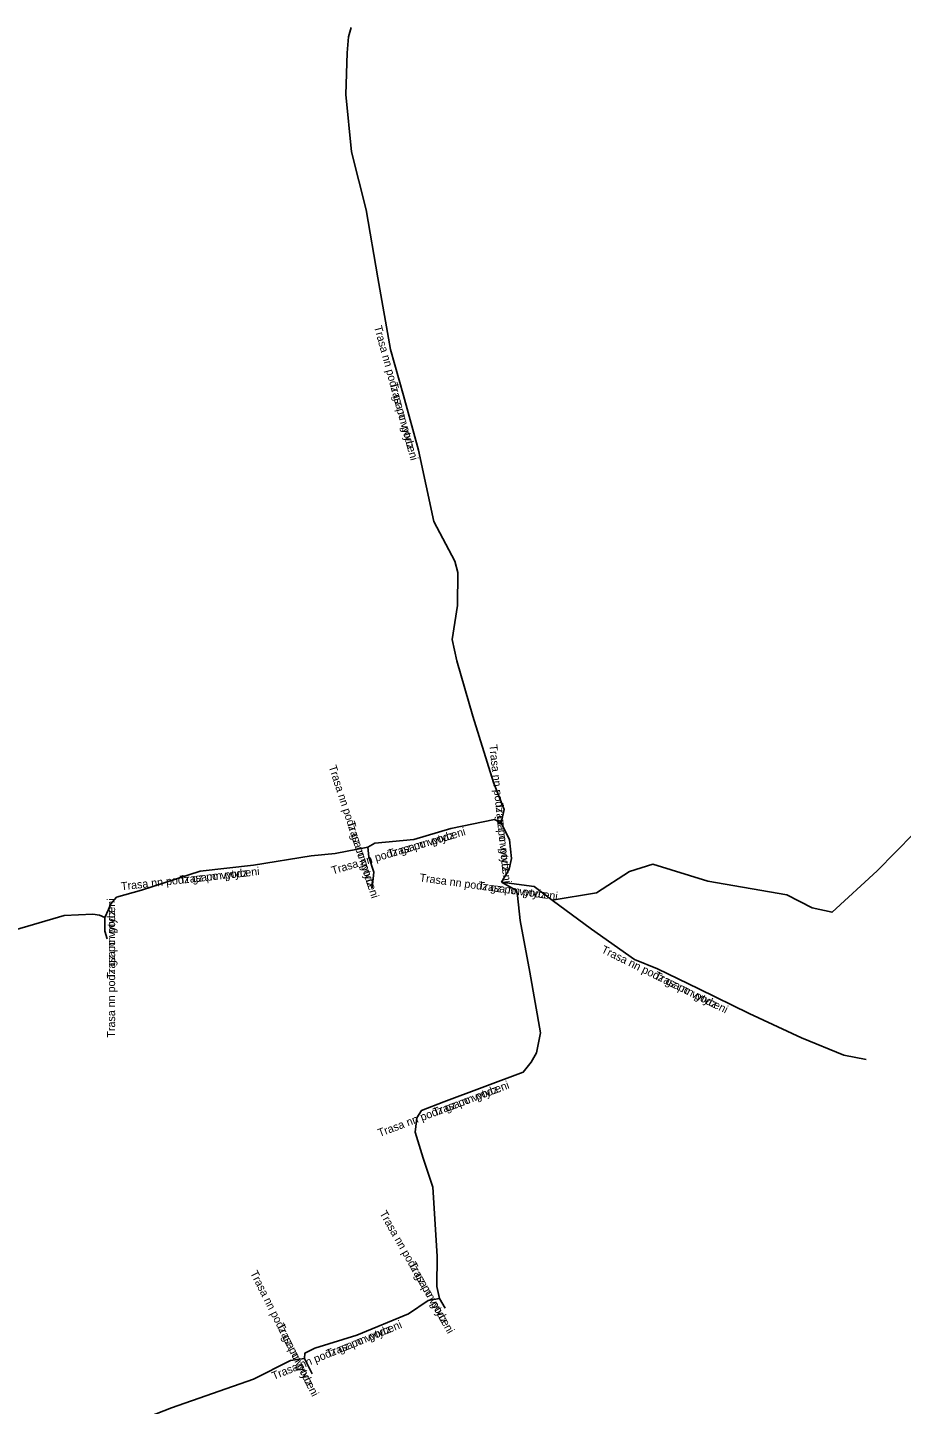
# Model space of a CAD drawing. Extents: x -876384 to -875659, y -1020218 to -1019588.
# Drawn here: x -875808.4 to -875753.8, y -1019934.5 to -1019848.4 of the extents above; entities that cross this region are included whole.
import ezdxf

# ---------------------------------------------------------------- set-up
doc = ezdxf.new("R2010")
doc.units = 0
doc.layers.add('Popiskový text - Ostatní atributy Trasy', color=7, linetype='Continuous')
doc.layers.add('Spojnice NN', color=7, linetype='Continuous')

msp = doc.modelspace()

# ---------------------------------------------------------------- linework, layer by layer
at = {"layer": 'Spojnice NN'}
for points in [[(-875788.21, -1019848.44), (-875788.36, -1019849.03), (-875788.44, -1019850.01), (-875788.54, -1019852.62), (-875788.18, -1019856.21), (-875787.27, -1019859.83), (-875786.53, -1019864.07), (-875785.75, -1019868.56), (-875784.93, -1019871.42), (-875783.99, -1019874.85), (-875783.03, -1019879.31), (-875781.73, -1019881.79), (-875781.53, -1019882.48), (-875781.57, -1019884.56), (-875781.9, -1019886.67), (-875781.6, -1019888.01), (-875780.6, -1019891.46), (-875779.31, -1019895.61), (-875778.65, -1019897.3), (-875778.83, -1019898.12)], [(-875788.21, -1019848.44), (-875788.36, -1019849.03), (-875788.44, -1019850.01), (-875788.54, -1019852.62), (-875788.18, -1019856.21), (-875787.27, -1019859.83), (-875786.53, -1019864.07), (-875785.75, -1019868.56), (-875784.93, -1019871.42), (-875783.99, -1019874.85), (-875783.03, -1019879.31), (-875781.73, -1019881.79), (-875781.53, -1019882.48), (-875781.57, -1019884.56), (-875781.9, -1019886.67), (-875781.6, -1019888.01), (-875780.6, -1019891.46), (-875779.31, -1019895.61), (-875778.65, -1019897.3), (-875778.83, -1019898.12)], [(-875787.16, -1019899.65), (-875786.73, -1019899.4), (-875784.29, -1019899.18), (-875781.97, -1019898.49), (-875779.24, -1019897.92), (-875778.83, -1019898.12)], [(-875787.16, -1019899.65), (-875786.73, -1019899.4), (-875784.29, -1019899.18), (-875781.97, -1019898.49), (-875779.24, -1019897.92), (-875778.83, -1019898.12)], [(-875778.83, -1019898.12), (-875778.31, -1019899.19), (-875778.19, -1019900.35), (-875778.33, -1019901.03), (-875778.82, -1019901.83)], [(-875778.83, -1019898.12), (-875778.31, -1019899.19), (-875778.19, -1019900.35), (-875778.33, -1019901.03), (-875778.82, -1019901.83)], [(-875775.64, -1019902.96), (-875772.88, -1019902.51), (-875770.81, -1019901.17), (-875769.37, -1019900.71), (-875765.93, -1019901.77), (-875760.99, -1019902.62), (-875759.42, -1019903.43), (-875758.17, -1019903.72), (-875755.35, -1019901.12), (-875753.07, -1019898.79)], [(-875775.64, -1019902.96), (-875772.88, -1019902.51), (-875770.81, -1019901.17), (-875769.37, -1019900.71), (-875765.93, -1019901.77), (-875760.99, -1019902.62), (-875759.42, -1019903.43), (-875758.17, -1019903.72), (-875755.35, -1019901.12), (-875753.07, -1019898.79)], [(-875803.59, -1019904.04), (-875803.35, -1019903.55), (-875803.2, -1019903.18), (-875802.85, -1019902.77), (-875801.3, -1019902.34), (-875797.64, -1019901.15), (-875794.3, -1019900.78), (-875790.7, -1019900.19), (-875789.2, -1019900.05), (-875787.16, -1019899.65)], [(-875803.59, -1019904.04), (-875803.35, -1019903.55), (-875803.2, -1019903.18), (-875802.85, -1019902.77), (-875801.3, -1019902.34), (-875797.64, -1019901.15), (-875794.3, -1019900.78), (-875790.7, -1019900.19), (-875789.2, -1019900.05), (-875787.16, -1019899.65)], [(-875786.89, -1019902.2), (-875786.78, -1019901.21), (-875787.09, -1019900.26), (-875787.16, -1019899.65)], [(-875786.89, -1019902.2), (-875786.78, -1019901.21), (-875787.09, -1019900.26), (-875787.16, -1019899.65)], [(-875782.68, -1019927.85), (-875782.86, -1019927.09), (-875782.83, -1019925.2), (-875783.11, -1019920.89), (-875783.7, -1019919.08), (-875784.2, -1019917.46), (-875784.1, -1019916.57), (-875783.8, -1019916.1), (-875782.41, -1019915.56), (-875777.45, -1019913.7), (-875776.95, -1019913.08), (-875776.62, -1019912.5), (-875776.38, -1019911.26), (-875777.04, -1019907.46), (-875777.65, -1019904.23), (-875777.82, -1019902.66), (-875777.88, -1019902.35), (-875778.82, -1019901.83)], [(-875782.68, -1019927.85), (-875782.86, -1019927.09), (-875782.83, -1019925.2), (-875783.11, -1019920.89), (-875783.7, -1019919.08), (-875784.2, -1019917.46), (-875784.1, -1019916.57), (-875783.8, -1019916.1), (-875782.41, -1019915.56), (-875777.45, -1019913.7), (-875776.95, -1019913.08), (-875776.62, -1019912.5), (-875776.38, -1019911.26), (-875777.04, -1019907.46), (-875777.65, -1019904.23), (-875777.82, -1019902.66), (-875777.88, -1019902.35), (-875778.82, -1019901.83)], [(-875778.82, -1019901.83), (-875776.77, -1019902.11), (-875775.64, -1019902.96)], [(-875778.82, -1019901.83), (-875776.77, -1019902.11), (-875775.64, -1019902.96)], [(-875775.64, -1019902.96), (-875773.19, -1019904.78), (-875770.51, -1019906.67), (-875769.07, -1019907.26), (-875766.48, -1019908.51), (-875763.35, -1019910.05), (-875760.07, -1019911.57), (-875757.43, -1019912.65), (-875756.04, -1019912.91)], [(-875775.64, -1019902.96), (-875773.19, -1019904.78), (-875770.51, -1019906.67), (-875769.07, -1019907.26), (-875766.48, -1019908.51), (-875763.35, -1019910.05), (-875760.07, -1019911.57), (-875757.43, -1019912.65), (-875756.04, -1019912.91)], [(-875833.52, -1019909.68), (-875833.35, -1019909.11), (-875832.4, -1019909.15), (-875831.35, -1019909.21), (-875829.35, -1019909.17), (-875826.46, -1019909.25), (-875823.96, -1019908.81), (-875821.35, -1019908.32), (-875820.55, -1019907.79), (-875819.78, -1019907.1), (-875818.99, -1019905.82), (-875817.61, -1019905.68), (-875816.97, -1019905.97), (-875813.82, -1019905.83), (-875809.59, -1019904.94), (-875806.12, -1019903.91), (-875804.33, -1019903.83), (-875803.91, -1019903.89), (-875803.59, -1019904.04)], [(-875833.52, -1019909.68), (-875833.35, -1019909.11), (-875832.4, -1019909.15), (-875831.35, -1019909.21), (-875829.35, -1019909.17), (-875826.46, -1019909.25), (-875823.96, -1019908.81), (-875821.35, -1019908.32), (-875820.55, -1019907.79), (-875819.78, -1019907.1), (-875818.99, -1019905.82), (-875817.61, -1019905.68), (-875816.97, -1019905.97), (-875813.82, -1019905.83), (-875809.59, -1019904.94), (-875806.12, -1019903.91), (-875804.33, -1019903.83), (-875803.91, -1019903.89), (-875803.59, -1019904.04)], [(-875803.44, -1019905.37), (-875803.59, -1019904.9), (-875803.59, -1019904.04)], [(-875803.44, -1019905.37), (-875803.59, -1019904.9), (-875803.59, -1019904.04)], [(-875791.12, -1019931.59), (-875791.09, -1019931.26), (-875790.47, -1019930.95), (-875787.85, -1019930.13), (-875784.61, -1019928.81), (-875783.39, -1019927.97), (-875782.68, -1019927.85)], [(-875791.12, -1019931.59), (-875791.09, -1019931.26), (-875790.47, -1019930.95), (-875787.85, -1019930.13), (-875784.61, -1019928.81), (-875783.39, -1019927.97), (-875782.68, -1019927.85)], [(-875782.68, -1019927.85), (-875782.34, -1019928.45)], [(-875782.68, -1019927.85), (-875782.34, -1019928.45)], [(-875824.43, -1019945.56), (-875824.36, -1019944.96), (-875824.14, -1019944.6), (-875822.21, -1019943.79), (-875817.1, -1019941.62), (-875813.27, -1019940.16), (-875810.76, -1019938.98), (-875807.49, -1019937.81), (-875804.59, -1019936.7), (-875799.42, -1019934.68), (-875794.3, -1019932.89), (-875791.98, -1019931.73), (-875791.12, -1019931.59)], [(-875824.43, -1019945.56), (-875824.36, -1019944.96), (-875824.14, -1019944.6), (-875822.21, -1019943.79), (-875817.1, -1019941.62), (-875813.27, -1019940.16), (-875810.76, -1019938.98), (-875807.49, -1019937.81), (-875804.59, -1019936.7), (-875799.42, -1019934.68), (-875794.3, -1019932.89), (-875791.98, -1019931.73), (-875791.12, -1019931.59)], [(-875790.64, -1019932.55), (-875791.12, -1019931.59)], [(-875790.64, -1019932.55), (-875791.12, -1019931.59)]]:
    msp.add_lwpolyline(points, dxfattribs=at)

# ---------------------------------------------------------------- texts
at = {"layer": 'Popiskový text - Ostatní atributy Trasy'}
for s, rotation, p in [('Trasa nn podz gz po vytyceni', 285.32577, (-875786.776, -1019867.141)), ('Trasa nn podz', 285.32577, (-875785.802, -1019870.695)), ('Trasa nn podz gz po vytyceni', 275.90614, (-875779.577, -1019893.26)), ('Trasa nn podz gz po vytyceni', 288.07232, (-875789.613, -1019894.623)), ('Trasa nn podz', 275.90614, (-875779.198, -1019896.926)), ('Trasa nn podz', 288.07232, (-875788.47, -1019898.126)), ('Trasa nn podz gz po vytyceni', 16.5632, (-875789.351, -1019901.363)), ('Trasa nn podz', 16.5632, (-875785.819, -1019900.313)), ('Trasa nn podz gz po vytyceni', 6.32136, (-875802.545, -1019902.347)), ('Trasa nn podz', 6.32136, (-875798.882, -1019901.941)), ('Trasa nn podz gz po vytyceni', 352.22236, (-875783.953, -1019901.785)), ('Trasa nn podz', 352.22236, (-875780.302, -1019902.284)), ('Trasa nn podz gz po vytyceni', 90, (-875802.94, -1019911.55)), ('Trasa nn podz', 90, (-875802.94, -1019907.865)), ('Trasa nn podz gz po vytyceni', 333.80222, (-875772.626, -1019906.211)), ('Trasa nn podz', 333.80222, (-875769.32, -1019907.838)), ('Trasa nn podz gz po vytyceni', 20.55605, (-875786.424, -1019917.759)), ('Trasa nn podz', 20.55605, (-875782.973, -1019916.465)), ('Trasa nn podz gz po vytyceni', 299.53878, (-875786.444, -1019922.526)), ('Trasa nn podz', 299.53878, (-875784.627, -1019925.732)), ('Trasa nn podz gz po vytyceni', 296.56505, (-875794.517, -1019926.249)), ('Trasa nn podz gz po vytyceni', 22.16635, (-875793.038, -1019932.945)), ('Trasa nn podz', 296.56505, (-875792.869, -1019929.545)), ('Trasa nn podz', 22.16635, (-875789.626, -1019931.555))]:
    msp.add_text(s, height=0.5, rotation=rotation, dxfattribs=at).set_placement(p)

doc.saveas('drawing.dxf')
